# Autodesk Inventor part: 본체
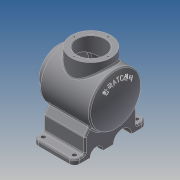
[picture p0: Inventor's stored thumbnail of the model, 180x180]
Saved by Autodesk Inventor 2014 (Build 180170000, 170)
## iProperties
Created: 2018-08
Part Number: 본체
Material: Generic
Document SubType Name: Modeling
Designer: kb542
Density: 1 g/cm^3
Appearance: Default
Author: kb542
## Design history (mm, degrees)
sketch "스케치1"
  geometry: L1 (-60, 27)-(-60, 38); L2 (-60, 38)-(-48, 38); L3 (-48, 38)-(-48, 50); L4 (-48, 50)-(48.671, 50); L5 (-38, 40)-(-38, 27); L6 (-38, 27)-(-60, 27); L7 (60, 0)-(-60, 0); L8 (42.163, 40)-(-38, 40); A1 r 116 centre (-56, 0) between (60, 0) and (48.671, 50); A2 r 106 centre (-56, 0) between (50, 0) and (42.163, 40); 2 further points
  constraints: 16 end point, 4 parallel, 4 point on circle, 2 centre point, 2 coincident, 2 perpendicular, 2 point on line, 1 horizontal alignment, 1 midpoint, 1 vertical, 1 vertical alignment
  dimensions: "d2" = 10 radial gap between concentric circles of A1 A2; "d3" = 116 radius of A1; "d4" = 120 distance from line of L7.start L1; "d5" = 12 distance of L1.end L2.end; "d6" = 100 diameter of L4 L7; "d7" = 76 diameter of L2 L7; "d8" = 54 diameter of L6 L7; "d9" = 22 distance of L5.end L1.start; "d10" = 80 diameter of L8 L7
revolve "회전1" sketch "스케치1" stored, may be unused: angle "d12" = 90 deg
node "작업 평면1"
sketch "스케치2"
  geometry: L1 (48, 50)-(48, -50) reference; C1 r 38 at (-2, 0); 2 further points
  constraints: 1 centre point, 1 coincident, 1 horizontal alignment, 1 midpoint
  dimensions: "d14" = 76 diameter of C1; "d75" = 50 distance from line of point (-2, 0) L1
extrude "돌출1" join sketch "스케치2" stored distance "d15" = 10; taper "d16" = 0 deg
sketch "스케치3"
  geometry: C1 r 38 at (0, 0) reference; C2 r 27 at (0, 0)
  constraints: 1 centre point, 1 coincident
  dimensions: "d17" = 54 diameter of C2
extrude "돌출2" cut sketch "스케치3" stored distance "d18" = 10; taper "d19" = 0 deg
sketch "스케치4"
  geometry: C1 r 27 at (0, 0) reference; 1 further point
  constraints: 1 vertical alignment
  dimensions: "d20" = 32.5 distance of C1.centre point (0, -32.5)
hole "구멍1" sketch "스케치4" at (0, -32.5) diameter "d21" = 3.242; stored, may be unused: countersink angle "d25" = 90 deg, drill point angle "d27" = 118 deg; dims "d22" = 8, "d23" = 4, "d24" = 2, "d26" = 10
sketch "스케치5"
  geometry: L1 (-40.304, -29.59)-(-50, -43.437); L2 (-50, -43.437)-(-50, -72); L3 (-50, -72)-(-70, -72); L4 (-70, -72)-(-70, -82); L5 (70, -82)-(70, -72); L6 (70, -72)-(50, -72); L7 (50, -72)-(50, -43.437); L8 (50, -43.437)-(40.304, -29.59); L9 (-70, -82)-(-40, -82); L10 (-5, -82)-(15, -82); L11 (40, -82)-(70, -82); L12 (-70, -72)-(-40.304, -29.59); L13 (40.304, -29.59)-(70, -72); A1 r 50 centre (0, 0) between (-40.304, -29.59) and (40.304, -29.59) reference; A2 r 17.5 centre (-22.5, -82) between (-5, -82) and (-40, -82); A3 r 12.5 centre (27.5, -82) between (40, -82) and (15, -82); 1 further point
  constraints: 26 end point, 10 perpendicular, 6 point on circle, 4 equal length, 3 horizontal alignment, 2 centre point, 1 collinear, 1 vertical
  dimensions: "d31" = 20 distance between parallel lines of L4 L2; "d32" = 35 deg angle of L5 L8; "d33" = 35 deg angle of L4 L1; "d40" = 10 distance between parallel lines of L11 L6; "d43" = 140 distance between parallel lines of L4 L5; "d44" = 70 distance from line of L4 point (0, 0); "d45" = 82 distance from line of A1.centre L11; "d76" = 17.5 radius of A2; "d77" = 12.5 radius of A3; "d78" = 27.5 horizontal distance of point (0, 0) A3.centre; "d79" = 22.5 horizontal distance of point (0, 0) A2.centre
extrude "돌출3" join sketch "스케치5" stored distance "d46" = 80; taper "d47" = 0 deg
sketch "스케치6"
  geometry: C1 r 38 at (0, 0) reference; 1 further point
  constraints: 1 horizontal alignment
  dimensions: "d48" = 32.5 distance of C1.centre point (-32.5, 0)
hole "구멍2" sketch "스케치6" at (-32.5, 0) diameter "d49" = 3.242; stored, may be unused: countersink angle "d53" = 90 deg, drill point angle "d55" = 118 deg; dims "d50" = 8, "d51" = 4, "d52" = 2, "d54" = 10
fillet "모깎기1" dims "d59" = 10
sketch "스케치7"
  geometry: L1 (80, -100)-(80, -110) reference; L2 (0, -100)-(80, -100) reference; L3 (0, -110)-(0, -100) reference; L4 (10, -120)-(70, -120) reference; A1 r 10 centre (10, 10) between (10, 20) and (0, 10) reference; A2 r 10 centre (70, 10) between (80, 10) and (70, 20) reference; A3 r 10 centre (70, -110) between (70, -120) and (80, -110) reference; A4 r 10 centre (10, -110) between (0, -110) and (10, -120) reference; 1 further point
hole "구멍3" sketch "스케치7" at (10, 10), (70, 10), (70, -110), (10, -110) diameter "d60" = 8; stored, may be unused: countersink angle "d64" = 90 deg, drill point angle "d66" = 118 deg; dims "d61" = 8, "d62" = 4, "d63" = 2, "d65" = 10
fillet "모깎기2" dims "d67" = 3
chamfer "모따기1" distance "d68" = 1; stored, may be unused: second distance "d69" = 2, angle "d70" = 45 deg
node "작업 평면2"
sketch "스케치8"
  geometry: C1 r 32.5 at (0, 0); 1 further point
  constraints: 1 centre point, 1 coincident, 1 other
  dimensions: "d72" = 65 diameter of C1
feature "엠보싱1" sketch "스케치8" dims "d73" = 0.5, "d74" = 0
node "솔리드1"
pattern_circular "원형 패턴1" dims angle "d29" = 360 deg
pattern_circular "원형 패턴2" dims angle "d57" = 360 deg
node "투영된 루프1"
other parameters: "d13" = 65, "d34" = 82, "d71" = -82.75
